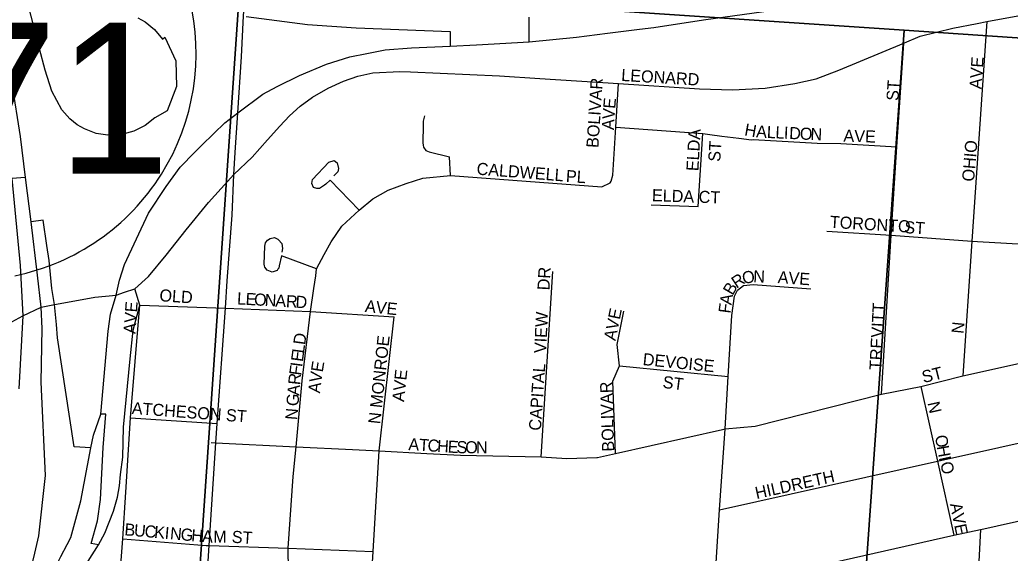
# Model space of a CAD drawing. Extents: x 0 to 34, y -6.2 to 22.
# Drawn here: x 7.576 to 8.351, y 18.759 to 19.177 of the extents above; entities that cross this region are included whole.
import ezdxf

# ---------------------------------------------------------------- set-up
doc = ezdxf.new("R2010")
doc.units = 0
for name, color, linetype in [('GM_X_City_Street', 7, 'Continuous'), ('GM_X_City_Street_Text', 7, 'Continuous'), ('GM_X_Interchange_Ramps', 7, 'Continuous'), ('GM_X_Interstate_Route', 7, 'Continuous'), ('GM_X_Interstate_Shield', 7, 'Continuous'), ('GM_X_Section', 7, 'Continuous')]:
    doc.layers.add(name, color=color, linetype=linetype)

msp = doc.modelspace()

# ---------------------------------------------------------------- linework, layer by layer
at = {"layer": 'GM_X_City_Street'}
for points in [[(7.74432, 19.07271), (7.74636, 19.10398), (7.74913, 19.14774), (7.75072, 19.17977), (7.7509, 19.18325)], [(8.32521, 19.17398), (8.33293, 19.17549), (8.39298, 19.18629)], [(8.26839, 19.15867), (8.28071, 19.164), (8.30612, 19.17026), (8.32521, 19.17398)], [(8.33293, 19.17549), (8.32106, 19.00342), (8.31401, 18.89785)], [(7.88142, 19.13597), (7.9511, 19.13297), (7.98272, 19.1307), (8.04436, 19.12679), (8.10792, 19.12274), (8.13379, 19.12187), (8.15921, 19.12327), (8.18253, 19.12675), (8.19925, 19.13057), (8.217, 19.13719), (8.26783, 19.15842), (8.26839, 19.15867)], [(8.25034, 18.88364), (8.25795, 19.00796), (8.26231, 19.0772), (8.26783, 19.15842)], [(7.7432, 19.05556), (7.75762, 19.06913), (7.76946, 19.0827), (7.77921, 19.0935), (7.78686, 19.10168), (7.79505, 19.10916), (7.8048, 19.11613), (7.81698, 19.12309), (7.82917, 19.12866), (7.84031, 19.13249), (7.85214, 19.1351), (7.87321, 19.13632), (7.88142, 19.13597)], [(8.03775, 19.04917), (8.03875, 19.05027), (8.03988, 19.05503), (8.04239, 19.09262), (8.04436, 19.12679)], [(7.89248, 19.10167), (7.89155, 19.09741), (7.89146, 19.09425), (7.89108, 19.08044), (7.89145, 19.07868), (7.89182, 19.07692), (7.89345, 19.07449), (7.89619, 19.0733), (7.91199, 19.06936)], [(8.04239, 19.09262), (8.11057, 19.0876), (8.11598, 19.08705), (8.12534, 19.08557), (8.1386, 19.08401), (8.14849, 19.08285), (8.14985, 19.083), (8.19989, 19.08012), (8.21863, 19.07978), (8.26231, 19.0772)], [(8.10682, 19.03061), (8.11057, 19.0876)], [(7.73807, 18.97224), (7.74174, 19.02373), (7.7432, 19.05556), (7.74432, 19.07271)], [(7.81858, 19.05129), (7.81534, 19.04807), (7.81423, 19.04732), (7.81026, 19.04465), (7.80814, 19.04467), (7.80549, 19.0455), (7.8043, 19.04868), (7.80489, 19.05171), (7.81765, 19.06537), (7.82168, 19.06665), (7.82419, 19.06478), (7.82511, 19.06036), (7.82457, 19.05762), (7.82157, 19.05446)], [(7.91282, 19.05472), (7.91199, 19.06936)], [(7.65764, 18.96343), (7.66552, 18.96605), (7.67636, 18.9758), (7.69009, 18.99255), (7.70575, 19.01238), (7.72333, 19.03361), (7.7432, 19.05556)], [(7.80333, 18.94842), (7.80574, 18.96634), (7.80749, 18.97628), (7.80791, 18.98167), (7.81392, 18.99295), (7.81948, 19.00288), (7.82766, 19.01516), (7.84136, 19.02774), (7.85192, 19.0365), (7.86391, 19.04322), (7.87823, 19.04848), (7.89109, 19.05286), (7.91282, 19.05472), (8.03139, 19.04585), (8.03775, 19.04917)], [(7.84136, 19.02774), (7.81858, 19.05129)], [(8.06992, 19.03175), (8.10682, 19.03061)], [(8.20763, 19.01124), (8.25795, 19.00796), (8.32106, 19.00342), (8.32548, 19.00315)], [(7.78038, 18.99196), (7.77875, 18.98418), (7.77835, 18.9823), (7.77773, 18.98137), (7.77712, 18.98044), (7.77324, 18.97916), (7.76928, 18.98077), (7.76754, 18.98292), (7.76727, 18.9841), (7.76701, 18.98527), (7.76741, 18.9994), (7.76805, 19.00204), (7.7696, 19.00416), (7.77153, 19.0056), (7.77504, 19.00613), (7.77767, 19.00495), (7.77826, 19.00432), (7.7808, 19.00154), (7.78131, 18.9976), (7.78084, 18.99478)], [(8.32548, 19.00315), (8.38443, 18.99963)], [(7.80791, 18.98167), (7.78038, 18.99196)], [(7.9839, 18.83444), (7.99305, 18.9797)], [(7.71574, 18.64078), (7.71788, 18.67689), (7.72169, 18.73196), (7.72388, 18.76503), (7.7292, 18.84541), (7.73021, 18.86071), (7.73656, 18.95093), (7.73807, 18.97224)], [(7.59239, 18.95169), (7.59239, 18.95169), (7.60269, 18.95389), (7.61001, 18.95511), (7.6342, 18.95946), (7.65091, 18.9612), (7.65764, 18.96343)], [(8.1332, 18.94504), (8.13521, 18.96035), (8.13766, 18.96504), (8.14227, 18.96877), (8.14985, 18.9695), (8.195, 18.96607)], [(8.12576, 18.85601), (8.12786, 18.85649), (8.15151, 18.85839), (8.25034, 18.88364), (8.28105, 18.88967), (8.31401, 18.89785), (8.37875, 18.91228), (8.44178, 18.9263), (8.46486, 18.93262), (8.49718, 18.9401), (8.56682, 18.95621), (8.57076, 18.95712), (8.57168, 18.95734), (8.57656, 18.9609)], [(7.56927, 18.94014), (7.57798, 18.94501), (7.59239, 18.95169)], [(7.65856, 18.80689), (7.66228, 18.86512), (7.66954, 18.95336)], [(7.66954, 18.95336), (7.73656, 18.95093), (7.80333, 18.94842), (7.86873, 18.94419)], [(7.78409, 18.65514), (7.78667, 18.69258), (7.78583, 18.76282), (7.78968, 18.81911), (7.79187, 18.84236), (7.79674, 18.89408), (7.80333, 18.94842)], [(8.04201, 18.83709), (8.04002, 18.89372), (8.04523, 18.90565), (8.04324, 18.92241), (8.04863, 18.94864)], [(7.84681, 18.67178), (7.85226, 18.76044), (7.8571, 18.83908), (7.86873, 18.94419)], [(8.09288, 18.26028), (8.09519, 18.3062), (8.09854, 18.36482), (8.10377, 18.45197), (8.11002, 18.56601), (8.11805, 18.70259), (8.11968, 18.7312), (8.1235, 18.7929), (8.12786, 18.85649), (8.13026, 18.89751), (8.1332, 18.94504)], [(8.04523, 18.90565), (8.13026, 18.89751)], [(8.28105, 18.88967), (8.29413, 18.83107), (8.30704, 18.77302)], [(7.66228, 18.86512), (7.73021, 18.86071)], [(8.02743, 18.83391), (8.02786, 18.83392), (8.04201, 18.83709), (8.12576, 18.85601)], [(8.1235, 18.7929), (8.29413, 18.83107), (8.39023, 18.85247), (8.39493, 18.85352)], [(7.72536, 18.84561), (7.7292, 18.84541), (7.79187, 18.84236), (7.83614, 18.8402), (7.8571, 18.83908), (7.89425, 18.83709), (7.9208, 18.83568), (7.9839, 18.83444), (8.00403, 18.83321), (8.02743, 18.83391)], [(7.64033, 18.66322), (7.63978, 18.66777), (7.64686, 18.68978), (7.65015, 18.70058), (7.65181, 18.71637), (7.65322, 18.72978), (7.65622, 18.77024), (7.65856, 18.80689)], [(8.32814, 18.77751), (8.39667, 18.79301), (8.40345, 18.79467), (8.41152, 18.79638)], [(8.14239, 18.73617), (8.18227, 18.74489), (8.24469, 18.75894), (8.30704, 18.77302), (8.32785, 18.77745), (8.32814, 18.77751)], [(8.32785, 18.77745), (8.32608, 18.7423), (8.31235, 18.63809), (8.31007, 18.60377), (8.30843, 18.5943), (8.30649, 18.59053), (8.30229, 18.5883), (8.29583, 18.58763), (8.28899, 18.47797), (8.28679, 18.44272), (8.28612, 18.3332), (8.28148, 18.28853), (8.28085, 18.27924)], [(7.65622, 18.77024), (7.72146, 18.76512), (7.72388, 18.76503)], [(7.72388, 18.76503), (7.78583, 18.76282), (7.85226, 18.76044)]]:
    msp.add_lwpolyline(points, dxfattribs=at)
at = {"layer": 'GM_X_Interchange_Ramps'}
for points in [[(7.66789, 19.17825), (7.67363, 19.17508), (7.68097, 19.16925), (7.68733, 19.16172), (7.68911, 19.16308), (7.69773, 19.14472), (7.69839, 19.12444), (7.69099, 19.10556), (7.68127, 19.10009), (7.67361, 19.09396), (7.66498, 19.08956), (7.65436, 19.08676), (7.64438, 19.08636), (7.63532, 19.08781), (7.62611, 19.09124), (7.62047, 19.09451), (7.61467, 19.09909), (7.6084, 19.10617), (7.60068, 19.12078), (7.59539, 19.13721), (7.59089, 19.15414), (7.581, 19.19313)], [(7.75279, 19.17939), (7.80085, 19.17307), (7.839, 19.17037), (7.91264, 19.16771), (7.91264, 19.15599)], [(7.97447, 19.15963), (7.97447, 19.17874)], [(7.5801, 19.05336), (7.56923, 19.05258), (7.57591, 18.98445), (7.57798, 18.94501), (7.57472, 18.88766)], [(7.63119, 18.84157), (7.61824, 18.8422), (7.60496, 18.92778), (7.60426, 18.93822), (7.60269, 18.95389), (7.60061, 18.96625), (7.59861, 18.98832), (7.59674, 19.00005), (7.59383, 19.01984), (7.58452, 19.01851)], [(7.57845, 18.66684), (7.59073, 18.66658), (7.59652, 18.68627), (7.59946, 18.69508), (7.60322, 18.70411), (7.61925, 18.73702), (7.63723, 18.76552), (7.64221, 18.77468), (7.649, 18.79198), (7.65206, 18.80298), (7.65354, 18.81171), (7.65455, 18.82056), (7.65625, 18.83417), (7.65682, 18.85762), (7.66209, 18.91134), (7.6644, 18.93374), (7.66954, 18.95336), (7.66552, 18.96605)], [(7.63723, 18.76552), (7.63144, 18.7666), (7.63633, 18.78441), (7.6387, 18.80094), (7.64079, 18.84174), (7.64302, 18.86802), (7.63906, 18.86788)]]:
    msp.add_lwpolyline(points, dxfattribs=at)
at = {"layer": 'GM_X_Interstate_Route'}
for points in [[(8.06075, 19.16945), (8.07215, 19.17086), (8.11095, 19.17672), (8.16588, 19.1842)], [(7.5801, 19.05336), (7.57604, 19.08544), (7.56297, 19.16785)], [(7.93325, 19.1572), (7.97447, 19.15963), (8.0114, 19.16304), (8.03576, 19.16635), (8.06075, 19.16945)], [(7.61263, 18.76586), (7.61545, 18.77142), (7.62328, 18.79995), (7.63119, 18.84157), (7.63317, 18.85148), (7.63906, 18.86788), (7.64465, 18.93283), (7.64656, 18.94623), (7.65091, 18.9612), (7.6537, 18.97286), (7.65753, 18.98505), (7.67636, 19.02539), (7.69014, 19.04617), (7.70127, 19.06135), (7.71261, 19.0731), (7.71785, 19.07827), (7.72739, 19.08768), (7.7361, 19.09618), (7.74636, 19.10398), (7.7659, 19.11848), (7.77721, 19.12448), (7.79451, 19.13313), (7.81571, 19.14212), (7.83399, 19.14777), (7.84733, 19.15047), (7.86169, 19.15318), (7.88227, 19.15493), (7.91264, 19.15599), (7.93325, 19.1572)], [(7.58722, 18.75905), (7.59048, 18.77269), (7.59567, 18.81976), (7.59242, 18.89296), (7.59312, 18.93509), (7.59239, 18.95169), (7.58944, 18.97672), (7.58452, 19.01851), (7.5801, 19.05336)], [(7.59928, 18.73976), (7.6078, 18.75636), (7.61263, 18.76586)], [(7.57641, 18.70824), (7.57845, 18.72231), (7.58722, 18.75905)]]:
    msp.add_lwpolyline(points, dxfattribs=at)
at = {"layer": 'GM_X_Interstate_Shield'}
msp.add_arc((7.53611, 19.15029), 0.17756, 281.53696, 14.19335, dxfattribs=at)
at = {"layer": 'GM_X_Section'}
for points in [[(8.82377, 19.63262), (8.78729, 19.13351), (8.26811, 19.16854), (7.74778, 19.20365), (7.78158, 19.69633)], [(7.25546, 19.23647), (7.74778, 19.20365), (7.67976, 18.21035), (7.19351, 18.24276)], [(7.74778, 19.20365), (8.26811, 19.16854), (8.19802, 18.176), (7.67976, 18.21035)], [(8.26811, 19.16854), (8.78729, 19.13351), (8.7151, 18.14174), (8.19802, 18.176)]]:
    msp.add_lwpolyline(points, close=True, dxfattribs=at)

# ---------------------------------------------------------------- texts
at = {"layer": 'GM_X_City_Street_Text'}
for s, height, rotation, p in [('AVE', 0.00947, 86.05739, (8.32862, 19.12224)), ('LEONARD', 0.00947, 356.53357, (8.04635, 19.12889)), ('BOLIVAR', 0.00947, 86.31007, (8.02862, 19.07621)), ('ST', 0.00947, 86.42535, (8.26363, 19.11306)), ('E', 0.00947, 85.43369, (8.04183, 19.10688)), ('V', 0.00947, 85.58117, (8.04119, 19.09858)), ('A', 0.00947, 86.8735, (8.04074, 19.09031)), ('H', 0.00947, 349.84766, (8.14256, 19.08633)), ('ELDA', 0.00947, 86.82218, (8.10696, 19.05805)), ('A', 0.00947, 356.69397, (8.15198, 19.08472)), ('L', 0.00947, 357.35266, (8.16042, 19.08423)), ('L', 0.00947, 357.36666, (8.16709, 19.08393)), ('I', 0.00947, 357.38797, (8.17375, 19.08362)), ('D', 0.00947, 357.35477, (8.17791, 19.08343)), ('O', 0.00947, 357.35477, (8.18623, 19.08304)), ('N', 0.00947, 357.35477, (8.19456, 19.08266)), ('AVE', 0.00947, 358.0261, (8.22046, 19.08139)), ('ST', 0.00947, 86.42535, (8.12405, 19.06538)), ('OHIO', 0.00947, 85.10355, (8.32279, 19.04977)), ('CALDWELL', 0.00947, 355.48564, (7.93304, 19.05556)), ('PL', 0.00947, 356.41261, (8.00301, 19.04973)), ('ELDA CT', 0.00947, 358.0261, (8.07046, 19.03473)), ('TORONTO', 0.00947, 356.53377, (8.20968, 19.01389)), ('ST', 0.00947, 356.42537, (8.26801, 19.00973)), ('DR', 0.00947, 86.82218, (7.9903, 18.96471)), ('O', 0.00947, 10.6841, (8.14217, 18.96973)), ('N', 0.00947, 357.87971, (8.14981, 18.97123)), ('AVE', 0.00947, 356.05688, (8.16886, 18.97056)), ('B', 0.00947, 59.65266, (8.1338, 18.96036)), ('R', 0.00947, 33.08392, (8.13679, 18.966)), ('OLD', 0.00947, 356.0574, (7.68469, 18.95639)), ('L', 0.00947, 356.77471, (7.74551, 18.95389)), ('E', 0.00947, 356.77471, (7.75216, 18.95352)), ('AVE', 0.00947, 85.90883, (7.66612, 18.93057)), ('O', 0.00947, 356.76318, (7.75882, 18.95314)), ('N', 0.00947, 356.78399, (7.76714, 18.95267)), ('A', 0.00947, 356.76318, (7.77546, 18.95221)), ('R', 0.00947, 356.77288, (7.78378, 18.95174)), ('D', 0.00947, 356.78501, (7.79127, 18.95131)), ('AVE', 0.00947, 353.88781, (7.84559, 18.94805)), ('A', 0.00947, 81.15578, (8.13283, 18.953)), ('TREVITT', 0.00947, 87.03705, (8.25029, 18.90221)), ('VIEW', 0.00947, 87.51167, (7.98779, 18.91552)), ('AVE', 0.00947, 78.30938, (8.04199, 18.92497)), ('F', 0.00947, 82.46493, (8.13196, 18.94645)), ('N', 0.00947, 84.29372, (8.31447, 18.93062)), ('D', 0.00947, 82.39235, (7.79901, 18.92179)), ('N MONROE', 0.00947, 83.83037, (7.8578, 18.85981)), ('E', 0.00947, 82.38369, (7.79724, 18.90857)), ('L', 0.00947, 82.41054, (7.79813, 18.91518)), ('E', 0.00947, 81.08559, (7.81281, 18.90039)), ('DEVOISE', 0.00947, 354.19259, (8.06308, 18.90639)), ('F', 0.00947, 82.49201, (7.79582, 18.89784)), ('I', 0.00947, 82.41402, (7.79669, 18.90444)), ('V', 0.00947, 81.70915, (7.81161, 18.89217)), ('AVE', 0.00947, 84.09771, (7.8765, 18.87729)), ('CAPITAL', 0.00947, 86.12003, (7.98362, 18.85473)), ('ST', 0.00947, 14.04267, (8.2833, 18.89218)), ('R', 0.00947, 83.82068, (7.79502, 18.89044)), ('BOLIVAR', 0.00947, 91.8466, (8.04112, 18.83872)), ('ST', 0.00947, 352.8649, (8.0786, 18.88855)), ('A', 0.00947, 85.31802, (7.79435, 18.8822)), ('A', 0.00947, 83.4715, (7.81067, 18.88397)), ('G', 0.00947, 85.33065, (7.79367, 18.87389)), ('N', 0.00947, 282.52367, (8.28631, 18.87667)), ('ATCHESON ST', 0.0094697, 355.74108, (7.66304, 18.86806)), ('N', 0.00947, 85.3398, (7.79279, 18.86309)), ('A', 0.00947, 356.52318, (7.87968, 18.83973)), ('T', 0.00947, 356.53133, (7.888, 18.83922)), ('C', 0.00947, 356.52516, (7.89465, 18.83882)), ('H', 0.00947, 356.52318, (7.90214, 18.83836)), ('E', 0.00947, 356.53133, (7.91046, 18.83786)), ('S', 0.00947, 358.32299, (7.91744, 18.83744)), ('O', 0.00947, 359.92533, (7.92439, 18.83724)), ('N', 0.00947, 359.99285, (7.93274, 18.83723)), ('O', 0.00947, 279.95101, (8.29216, 18.85075)), ('H', 0.00947, 280.11829, (8.29361, 18.84251)), ('I', 0.00947, 282.56346, (8.29515, 18.83387)), ('HILDRETH', 0.00947, 12.43893, (8.15252, 18.80135)), ('O', 0.00947, 284.85951, (8.29616, 18.8294)), ('AVE', 0.00947, 281.69062, (8.30381, 18.79747)), ('B', 0.00947, 355.01448, (7.65723, 18.77306)), ('U', 0.00947, 355.02656, (7.6647, 18.77241)), ('C', 0.00947, 355.01448, (7.673, 18.77168)), ('K', 0.00947, 355.02656, (7.68047, 18.77103)), ('I', 0.00947, 355.05487, (7.68878, 18.77031)), ('N', 0.00947, 355.00943, (7.69293, 18.76995)), ('G', 0.00947, 355.01469, (7.70123, 18.76922)), ('H', 0.00947, 355.02656, (7.70953, 18.7685)), ('A', 0.00947, 356.73898, (7.71815, 18.76775)), ('M', 0.00947, 359.82782, (7.72702, 18.76726)), ('ST', 0.00947, 356.42537, (7.74135, 18.76723))]:
    msp.add_text(s, height=height, rotation=rotation, dxfattribs=at).set_placement(p)
at = {"layer": 'GM_X_Interstate_Shield'}
msp.add_text('71', height=0.118371, dxfattribs=at).set_placement((7.51694, 19.05622))

doc.saveas('drawing.dxf')
